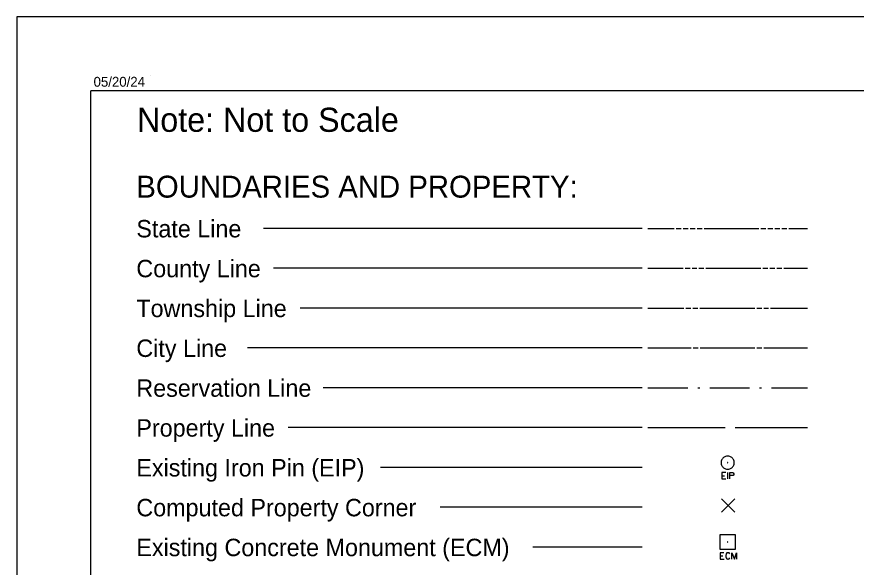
# Model space of a CAD drawing. Extents: x 1552903 to 1553044, y 811448 to 811540.
# Drawn here: x 1552902.56 to 1552937.98, y 811516.86 to 811540.09 of the extents above; entities that cross this region are included whole.
import ezdxf

# ---------------------------------------------------------------- set-up
doc = ezdxf.new("R2010")
doc.units = 0
for name, color, linetype in [('Exist DTM Breakline', 7, 'Continuous'), ('Exist Structure Major Bridge WW', 7, 'Continuous'), ('z - Construction', 7, 'Continuous')]:
    doc.layers.add(name, color=color, linetype=linetype)

msp = doc.modelspace()

# ---------------------------------------------------------------- linework, layer by layer
at = {"layer": 'Exist DTM Breakline'}
for p, q in [((1552928.953, 811531.156), (1552912.979, 811531.156)), ((1552929.195, 811531.156), (1552930.305, 811531.156)), ((1552930.389, 811531.156), (1552930.599, 811531.156)), ((1552930.683, 811531.156), (1552930.893, 811531.156)), ((1552930.977, 811531.156), (1552931.188, 811531.156)), ((1552931.272, 811531.156), (1552931.482, 811531.156)), ((1552931.566, 811531.156), (1552933.878, 811531.156)), ((1552933.962, 811531.156), (1552934.172, 811531.156)), ((1552934.256, 811531.156), (1552934.467, 811531.156)), ((1552934.551, 811531.156), (1552934.761, 811531.156)), ((1552934.845, 811531.156), (1552935.055, 811531.156)), ((1552935.139, 811531.156), (1552935.921, 811531.156)), ((1552928.953, 811529.475), (1552913.399, 811529.475)), ((1552929.195, 811529.475), (1552930.674, 811529.475)), ((1552930.758, 811529.475), (1552930.968, 811529.475)), ((1552931.052, 811529.475), (1552931.262, 811529.475)), ((1552931.346, 811529.475), (1552931.556, 811529.475)), ((1552931.64, 811529.475), (1552933.953, 811529.475)), ((1552934.037, 811529.475), (1552934.247, 811529.475)), ((1552934.331, 811529.475), (1552934.541, 811529.475)), ((1552934.625, 811529.475), (1552934.835, 811529.475)), ((1552934.92, 811529.475), (1552935.921, 811529.475)), ((1552928.953, 811527.793), (1552914.517, 811527.793)), ((1552929.195, 811527.793), (1552930.712, 811527.793)), ((1552930.797, 811527.793), (1552931.007, 811527.793)), ((1552931.091, 811527.793), (1552931.301, 811527.793)), ((1552931.385, 811527.793), (1552933.697, 811527.793)), ((1552933.781, 811527.793), (1552933.992, 811527.793)), ((1552934.076, 811527.793), (1552934.286, 811527.793)), ((1552934.37, 811527.793), (1552935.921, 811527.793)), ((1552928.953, 811526.112), (1552912.3, 811526.112)), ((1552929.195, 811526.112), (1552931.014, 811526.112)), ((1552931.098, 811526.112), (1552931.308, 811526.112)), ((1552931.392, 811526.112), (1552933.705, 811526.112)), ((1552933.789, 811526.112), (1552933.999, 811526.112)), ((1552934.083, 811526.112), (1552935.921, 811526.112)), ((1552928.953, 811524.43), (1552915.494, 811524.43)), ((1552929.195, 811524.43), (1552930.876, 811524.43)), ((1552931.297, 811524.43), (1552931.381, 811524.43)), ((1552931.801, 811524.43), (1552933.483, 811524.43)), ((1552933.903, 811524.43), (1552933.987, 811524.43)), ((1552934.408, 811524.43), (1552935.921, 811524.43)), ((1552928.953, 811522.748), (1552914.015, 811522.748)), ((1552929.195, 811522.748), (1552932.453, 811522.748)), ((1552932.873, 811522.748), (1552935.921, 811522.748)), ((1552928.953, 811521.067), (1552917.915, 811521.067)), ((1552932.317, 811520.719), (1552932.427, 811520.719)), ((1552932.559, 811520.583), (1552932.559, 811520.853)), ((1552932.853, 811519.182), (1552932.298, 811519.738)), ((1552932.298, 811519.182), (1552932.853, 811519.738)), ((1552928.953, 811519.385), (1552920.424, 811519.385)), ((1552928.953, 811517.704), (1552924.343, 811517.704)), ((1552932.241, 811517.334), (1552932.351, 811517.334))]:
    msp.add_line(p, q, dxfattribs=at)
for points in [[(1552932.835, 811521.269), (1552932.833, 811521.304), (1552932.826, 811521.338), (1552932.815, 811521.372), (1552932.802, 811521.403), (1552932.781, 811521.432), (1552932.759, 811521.459), (1552932.735, 811521.483), (1552932.705, 811521.503), (1552932.676, 811521.521), (1552932.643, 811521.532), (1552932.609, 811521.541), (1552932.576, 811521.546), (1552932.54, 811521.546), (1552932.504, 811521.541), (1552932.471, 811521.532), (1552932.44, 811521.521), (1552932.408, 811521.503), (1552932.379, 811521.483), (1552932.355, 811521.459), (1552932.332, 811521.432), (1552932.314, 811521.403), (1552932.299, 811521.372), (1552932.288, 811521.338), (1552932.281, 811521.304), (1552932.279, 811521.269), (1552932.281, 811521.233), (1552932.288, 811521.199), (1552932.299, 811521.166), (1552932.314, 811521.135), (1552932.332, 811521.106), (1552932.355, 811521.079), (1552932.379, 811521.054), (1552932.408, 811521.034), (1552932.44, 811521.016), (1552932.471, 811521.005), (1552932.504, 811520.996), (1552932.54, 811520.992), (1552932.576, 811520.992), (1552932.609, 811520.996), (1552932.643, 811521.005), (1552932.676, 811521.016), (1552932.705, 811521.034), (1552932.735, 811521.054), (1552932.759, 811521.079), (1552932.781, 811521.106), (1552932.802, 811521.135), (1552932.815, 811521.166), (1552932.826, 811521.199), (1552932.833, 811521.233), (1552932.835, 811521.269)], [(1552932.562, 811521.275), (1552932.556, 811521.278), (1552932.551, 811521.273), (1552932.549, 811521.266), (1552932.553, 811521.262), (1552932.56, 811521.26), (1552932.565, 811521.264), (1552932.567, 811521.271), (1552932.562, 811521.275)], [(1552932.472, 811520.853), (1552932.317, 811520.853), (1552932.317, 811520.583), (1552932.483, 811520.583)], [(1552932.648, 811520.583), (1552932.648, 811520.853), (1552932.756, 811520.853), (1552932.788, 811520.842), (1552932.815, 811520.8), (1552932.815, 811520.774), (1552932.79, 811520.732), (1552932.756, 811520.721), (1552932.648, 811520.721)], [(1552932.242, 811518.233), (1552932.872, 811518.233), (1552932.872, 811517.603), (1552932.242, 811517.603), (1552932.242, 811518.233)], [(1552932.556, 811517.925), (1552932.553, 811517.922), (1552932.553, 811517.916), (1552932.559, 811517.91), (1552932.565, 811517.913), (1552932.568, 811517.919), (1552932.562, 811517.925), (1552932.556, 811517.925)], [(1552932.395, 811517.467), (1552932.241, 811517.467), (1552932.241, 811517.198), (1552932.406, 811517.198)], [(1552932.649, 811517.414), (1552932.616, 811517.459), (1552932.582, 811517.467), (1552932.558, 811517.467), (1552932.527, 811517.459), (1552932.491, 811517.414), (1552932.482, 811517.355), (1552932.482, 811517.323), (1552932.482, 811517.302), (1552932.484, 811517.283), (1552932.491, 811517.249), (1552932.527, 811517.207), (1552932.558, 811517.198), (1552932.577, 811517.198), (1552932.613, 811517.207), (1552932.649, 811517.249)], [(1552932.736, 811517.198), (1552932.736, 811517.467), (1552932.838, 811517.198), (1552932.935, 811517.467), (1552932.935, 811517.198)]]:
    msp.add_lwpolyline(points, dxfattribs=at)
at = {"layer": 'Exist Structure Major Bridge WW'}
for p, q in [((1552908.185, 811537.59), (1552908.185, 811537.59)), ((1552905.688, 811451.545), (1552905.688, 811536.962)), ((1553041.105, 811536.962), (1552905.688, 811536.962))]:
    msp.add_line(p, q, dxfattribs=at)
at = {"layer": 'z - Construction'}
for p, q in [((1553044.23, 811540.087), (1552902.563, 811540.087)), ((1552902.563, 811540.087), (1552902.563, 811448.42))]:
    msp.add_line(p, q, dxfattribs=at)

# ---------------------------------------------------------------- texts
at = {"layer": 'Exist DTM Breakline'}
for s, height, p in [('Note: Not to Scale', 1.01798, (1552907.635, 811535.231)), ('BOUNDARIES AND PROPERTY:', 0.92486, (1552907.607, 811532.455)), ('State Line', 0.7357, (1552907.608, 811530.775)), ('County Line', 0.73569, (1552907.608, 811529.093)), ('Township Line', 0.73569, (1552907.608, 811527.412)), ('City Line', 0.7357, (1552907.608, 811525.73)), ('Reservation Line', 0.73569, (1552907.608, 811524.049)), ('Property Line', 0.73569, (1552907.608, 811522.367)), ('Existing Iron Pin (EIP)', 0.73569, (1552907.608, 811520.685)), ('Computed Property Corner', 0.73569, (1552907.608, 811519.004)), ('Existing Concrete Monument (ECM)', 0.73569, (1552907.608, 811517.322))]:
    msp.add_text(s, height=height, dxfattribs=at).set_placement(p)
at = {"layer": 'Exist Structure Major Bridge WW'}
msp.add_text('05/20/24', height=0.4167, rotation=0, dxfattribs=at).set_placement((1552905.803, 811537.135))

doc.saveas('drawing.dxf')
